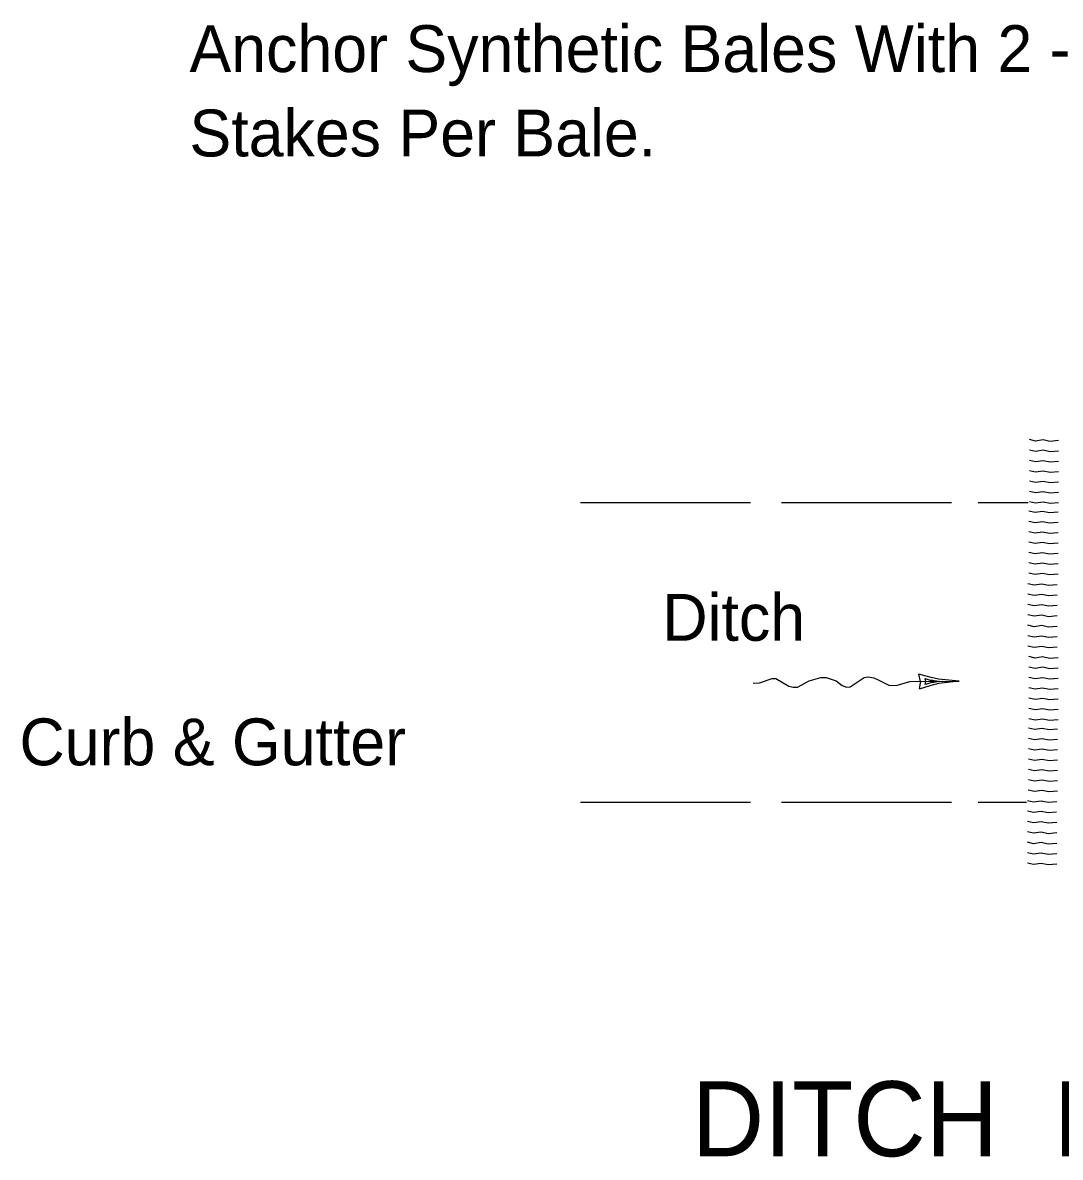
# Model space of a CAD drawing. Extents: x 539344 to 540004, y 1574686 to 1575110.
# Drawn here: x 539856.2 to 539911.6, y 1574750.2 to 1574810.7 of the extents above; entities that cross this region are included whole.
import ezdxf

# ---------------------------------------------------------------- set-up
doc = ezdxf.new("R2010")
doc.units = 0
doc.layers.add('Default', color=7, linetype='Continuous')

msp = doc.modelspace()

# ---------------------------------------------------------------- linework, layer by layer
at = {"layer": 'Default'}
for p, q in [((539885.983, 1574785.07), (539895.049, 1574785.07)), ((539896.715, 1574785.07), (539905.781, 1574785.07)), ((539907.191, 1574785.07), (539909.869, 1574785.07)), ((539904.121, 1574775.534), (539904.041, 1574775.918)), ((539904.121, 1574775.534), (539904.047, 1574775.148)), ((539885.983, 1574769.096), (539895.049, 1574769.096)), ((539896.715, 1574769.096), (539905.781, 1574769.096)), ((539907.191, 1574769.096), (539909.779, 1574769.096))]:
    msp.add_line(p, q, dxfattribs=at)
for points in [[(539911.489, 1574788.372), (539911.029, 1574788.336), (539910.663, 1574788.41), (539910.259, 1574788.354), (539909.929, 1574788.428)], [(539911.491, 1574787.82), (539911.033, 1574787.784), (539910.667, 1574787.858), (539910.259, 1574787.8), (539909.931, 1574787.874)], [(539911.493, 1574787.266), (539911.035, 1574787.228), (539910.667, 1574787.302), (539910.261, 1574787.246), (539909.931, 1574787.32)], [(539911.491, 1574786.714), (539911.031, 1574786.678), (539910.665, 1574786.752), (539910.259, 1574786.696), (539909.931, 1574786.77)], [(539911.491, 1574786.16), (539911.033, 1574786.126), (539910.667, 1574786.198), (539910.259, 1574786.144), (539909.931, 1574786.216)], [(539911.493, 1574785.606), (539911.035, 1574785.572), (539910.667, 1574785.644), (539910.261, 1574785.59), (539909.931, 1574785.662)], [(539911.493, 1574785.054), (539911.035, 1574785.018), (539910.667, 1574785.09), (539910.261, 1574785.036), (539909.931, 1574785.108)], [(539911.463, 1574784.566), (539911.005, 1574784.528), (539910.637, 1574784.602), (539910.233, 1574784.546), (539909.903, 1574784.62)], [(539911.465, 1574784.014), (539911.005, 1574783.976), (539910.639, 1574784.05), (539910.233, 1574783.994), (539909.905, 1574784.068)], [(539911.463, 1574783.46), (539911.005, 1574783.422), (539910.637, 1574783.496), (539910.233, 1574783.44), (539909.903, 1574783.514)], [(539911.463, 1574782.908), (539911.005, 1574782.87), (539910.637, 1574782.944), (539910.233, 1574782.89), (539909.903, 1574782.964)], [(539911.463, 1574782.354), (539911.005, 1574782.318), (539910.637, 1574782.392), (539910.233, 1574782.336), (539909.903, 1574782.41)], [(539911.463, 1574781.8), (539911.005, 1574781.762), (539910.637, 1574781.836), (539910.233, 1574781.78), (539909.903, 1574781.854)], [(539911.463, 1574781.248), (539911.001, 1574781.212), (539910.637, 1574781.288), (539910.231, 1574781.23), (539909.901, 1574781.304)], [(539911.417, 1574780.678), (539910.957, 1574780.642), (539910.589, 1574780.716), (539910.185, 1574780.66), (539909.853, 1574780.734)], [(539911.411, 1574780.128), (539910.955, 1574780.09), (539910.587, 1574780.164), (539910.181, 1574780.108), (539909.851, 1574780.182)], [(539911.415, 1574779.576), (539910.955, 1574779.538), (539910.589, 1574779.612), (539910.181, 1574779.558), (539909.853, 1574779.63)], [(539911.417, 1574779.022), (539910.957, 1574778.984), (539910.589, 1574779.058), (539910.185, 1574779.004), (539909.853, 1574779.076)], [(539911.417, 1574778.468), (539910.957, 1574778.43), (539910.589, 1574778.506), (539910.185, 1574778.45), (539909.853, 1574778.524)], [(539911.417, 1574777.916), (539910.957, 1574777.878), (539910.589, 1574777.952), (539910.185, 1574777.898), (539909.853, 1574777.97)], [(539911.415, 1574777.362), (539910.955, 1574777.326), (539910.589, 1574777.4), (539910.181, 1574777.344), (539909.853, 1574777.416)], [(539911.463, 1574776.798), (539911.003, 1574776.762), (539910.637, 1574776.836), (539910.233, 1574776.78), (539909.903, 1574776.854)], [(539895.193, 1574775.446), (539895.539, 1574775.45), (539896.215, 1574775.686), (539896.409, 1574775.68), (539897.105, 1574775.28), (539897.321, 1574775.224), (539897.557, 1574775.222), (539898.175, 1574775.564), (539898.805, 1574775.74), (539899.089, 1574775.742), (539899.615, 1574775.564), (539899.949, 1574775.308), (539900.177, 1574775.228), (539900.367, 1574775.248), (539901.119, 1574775.734), (539901.327, 1574775.774), (539901.625, 1574775.728), (539901.861, 1574775.61), (539902.435, 1574775.332), (539902.815, 1574775.314), (539903.557, 1574775.52), (539906.177, 1574775.542)], [(539906.177, 1574775.542), (539905.079, 1574775.652), (539904.615, 1574775.76), (539904.041, 1574775.918)], [(539911.465, 1574776.246), (539911.007, 1574776.21), (539910.641, 1574776.284), (539910.233, 1574776.226), (539909.905, 1574776.3)], [(539906.177, 1574775.542), (539905.081, 1574775.412), (539904.619, 1574775.296), (539904.047, 1574775.12)], [(539905.303, 1574775.534), (539905.013, 1574775.508), (539904.833, 1574775.47), (539904.679, 1574775.452), (539904.559, 1574775.416), (539904.379, 1574775.372), (539904.411, 1574775.528), (539904.377, 1574775.69), (539904.523, 1574775.632), (539904.633, 1574775.606), (539904.755, 1574775.59), (539904.867, 1574775.566), (539904.969, 1574775.558), (539905.089, 1574775.542), (539905.303, 1574775.534)], [(539911.467, 1574775.692), (539911.009, 1574775.654), (539910.641, 1574775.728), (539910.235, 1574775.672), (539909.905, 1574775.746)], [(539911.465, 1574775.14), (539911.005, 1574775.104), (539910.639, 1574775.178), (539910.233, 1574775.122), (539909.905, 1574775.196)], [(539911.465, 1574774.586), (539911.007, 1574774.552), (539910.641, 1574774.624), (539910.233, 1574774.57), (539909.905, 1574774.642)], [(539911.467, 1574774.032), (539911.009, 1574773.998), (539910.641, 1574774.07), (539910.235, 1574774.016), (539909.905, 1574774.088)], [(539911.467, 1574773.48), (539911.009, 1574773.444), (539910.641, 1574773.516), (539910.235, 1574773.462), (539909.905, 1574773.534)], [(539911.437, 1574772.992), (539910.979, 1574772.954), (539910.611, 1574773.028), (539910.207, 1574772.972), (539909.877, 1574773.046)], [(539911.439, 1574772.44), (539910.979, 1574772.402), (539910.613, 1574772.476), (539910.207, 1574772.42), (539909.879, 1574772.494)], [(539911.437, 1574771.886), (539910.979, 1574771.848), (539910.611, 1574771.922), (539910.207, 1574771.866), (539909.877, 1574771.94)], [(539911.437, 1574771.334), (539910.979, 1574771.296), (539910.611, 1574771.37), (539910.207, 1574771.316), (539909.877, 1574771.39)], [(539911.437, 1574770.78), (539910.979, 1574770.744), (539910.611, 1574770.818), (539910.207, 1574770.762), (539909.877, 1574770.836)], [(539911.437, 1574769.674), (539910.975, 1574769.638), (539910.611, 1574769.714), (539910.205, 1574769.656), (539909.875, 1574769.73)], [(539911.437, 1574770.226), (539910.979, 1574770.188), (539910.611, 1574770.262), (539910.207, 1574770.206), (539909.877, 1574770.28)], [(539911.391, 1574769.104), (539910.931, 1574769.068), (539910.563, 1574769.142), (539910.159, 1574769.086), (539909.827, 1574769.16)], [(539911.385, 1574768.554), (539910.929, 1574768.516), (539910.561, 1574768.59), (539910.155, 1574768.534), (539909.825, 1574768.608)], [(539911.389, 1574768.002), (539910.929, 1574767.964), (539910.563, 1574768.038), (539910.155, 1574767.984), (539909.827, 1574768.056)], [(539911.391, 1574767.448), (539910.931, 1574767.41), (539910.563, 1574767.484), (539910.159, 1574767.43), (539909.827, 1574767.502)], [(539911.391, 1574766.894), (539910.931, 1574766.856), (539910.563, 1574766.932), (539910.159, 1574766.876), (539909.827, 1574766.95)], [(539911.391, 1574766.342), (539910.931, 1574766.304), (539910.563, 1574766.378), (539910.159, 1574766.324), (539909.827, 1574766.396)], [(539911.389, 1574765.788), (539910.929, 1574765.752), (539910.563, 1574765.826), (539910.155, 1574765.77), (539909.827, 1574765.842)]]:
    msp.add_lwpolyline(points, dxfattribs=at)

# ---------------------------------------------------------------- texts
for s, height, p in [('Anchor Synthetic Bales With 2 - 2" x 2" x 4\'', 2.5, (539865.12, 1574808.031)), ('Stakes Per Bale.', 2.5, (539865.12, 1574803.531)), ('Ditch', 2.5, (539890.348, 1574777.699)), ('Curb & Gutter', 2.5, (539856.052, 1574771.057)), ('DITCH  BOTTOM  INLET', 4, (539891.918, 1574750.207))]:
    msp.add_text(s, height=height, dxfattribs=at).set_placement(p)

doc.saveas('drawing.dxf')
